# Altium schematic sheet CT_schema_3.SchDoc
size 218 x 258 mm
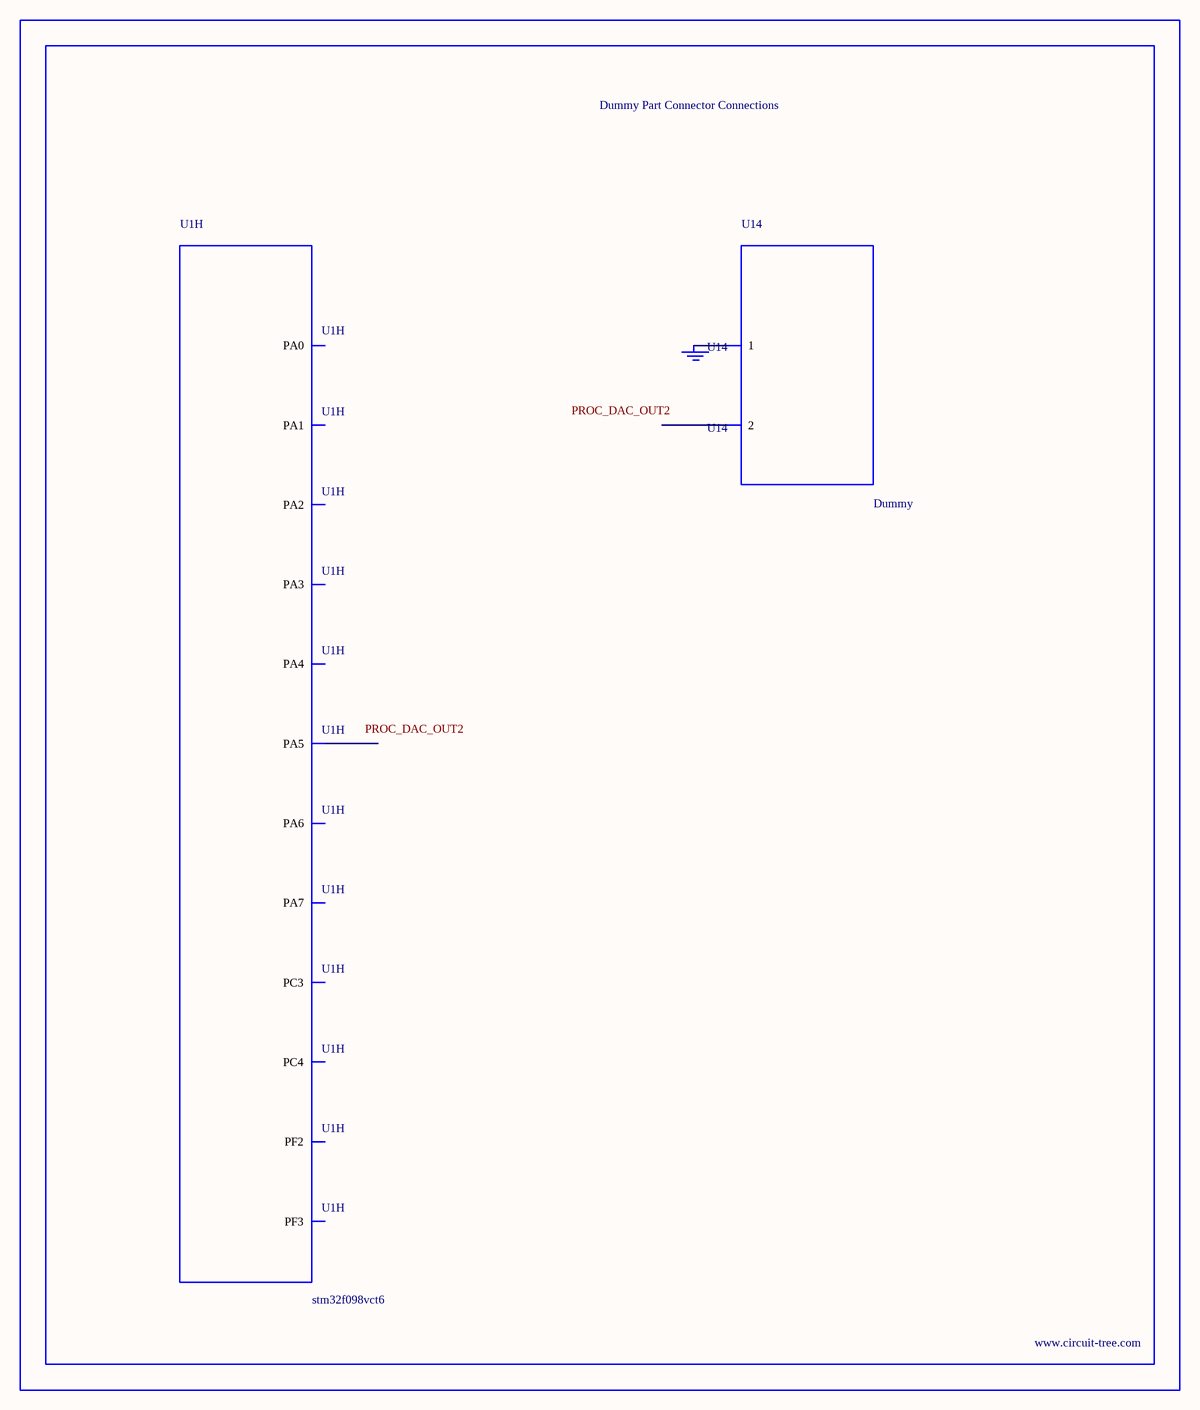
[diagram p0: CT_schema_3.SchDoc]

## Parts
BORDER2  (no value)
GND_INSTANCE_2_0  (no value)
U1  stm32f098vct6  [LQFP100]  (part H of 8)
U14  Dummy  [DUMMY_PACKAGE_113]

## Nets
NetGND_INSTANCE_2_0_0: GND_INSTANCE_2_0.0(GND) U14.1

Not connected (* = marked no-connect by the designer): U1 18(PC3) 19(PF2) 22(PF3) 23(PA0) 24(PA1) 25(PA2) 26(PA3) 29(PA4) 30(PA5) 31(PA6) 32(PA7) 33(PC4); U14 2

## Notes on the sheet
- Labels drawn without touching a wire or pin: PROC_DAC_OUT2

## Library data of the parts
BORDER2 = BORDER_PAGE2
GND_INSTANCE_2_0 = GND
